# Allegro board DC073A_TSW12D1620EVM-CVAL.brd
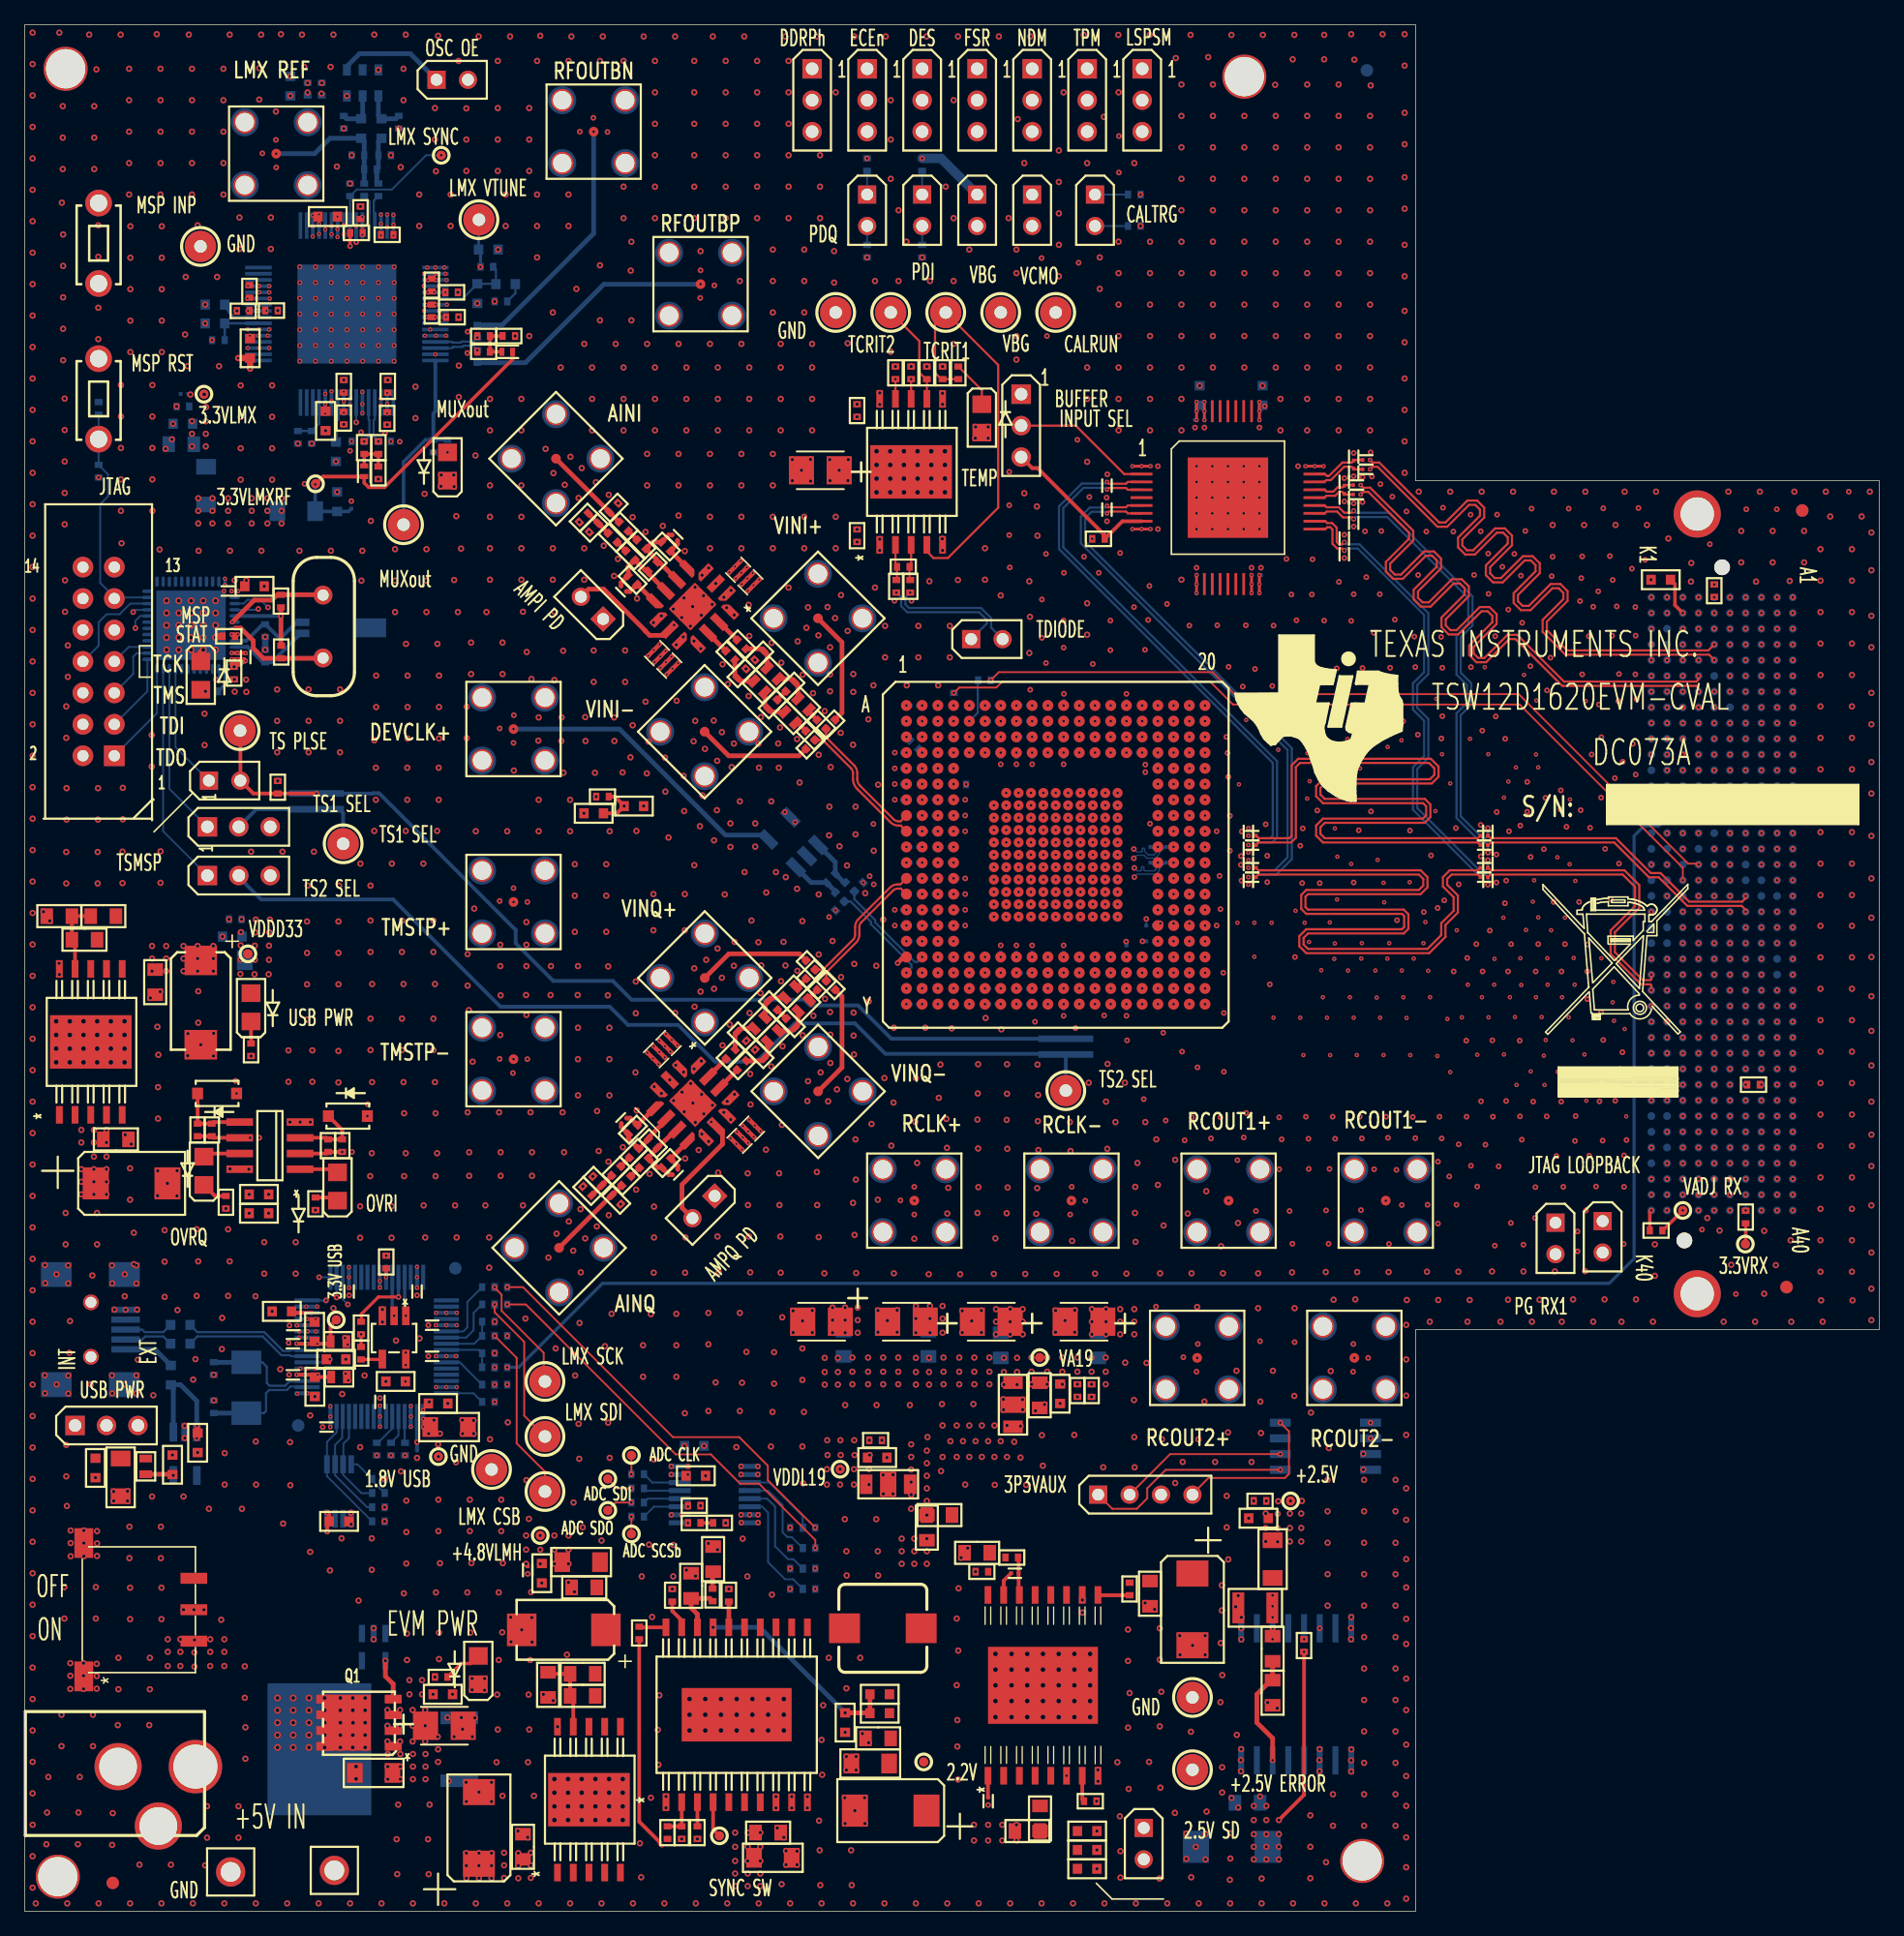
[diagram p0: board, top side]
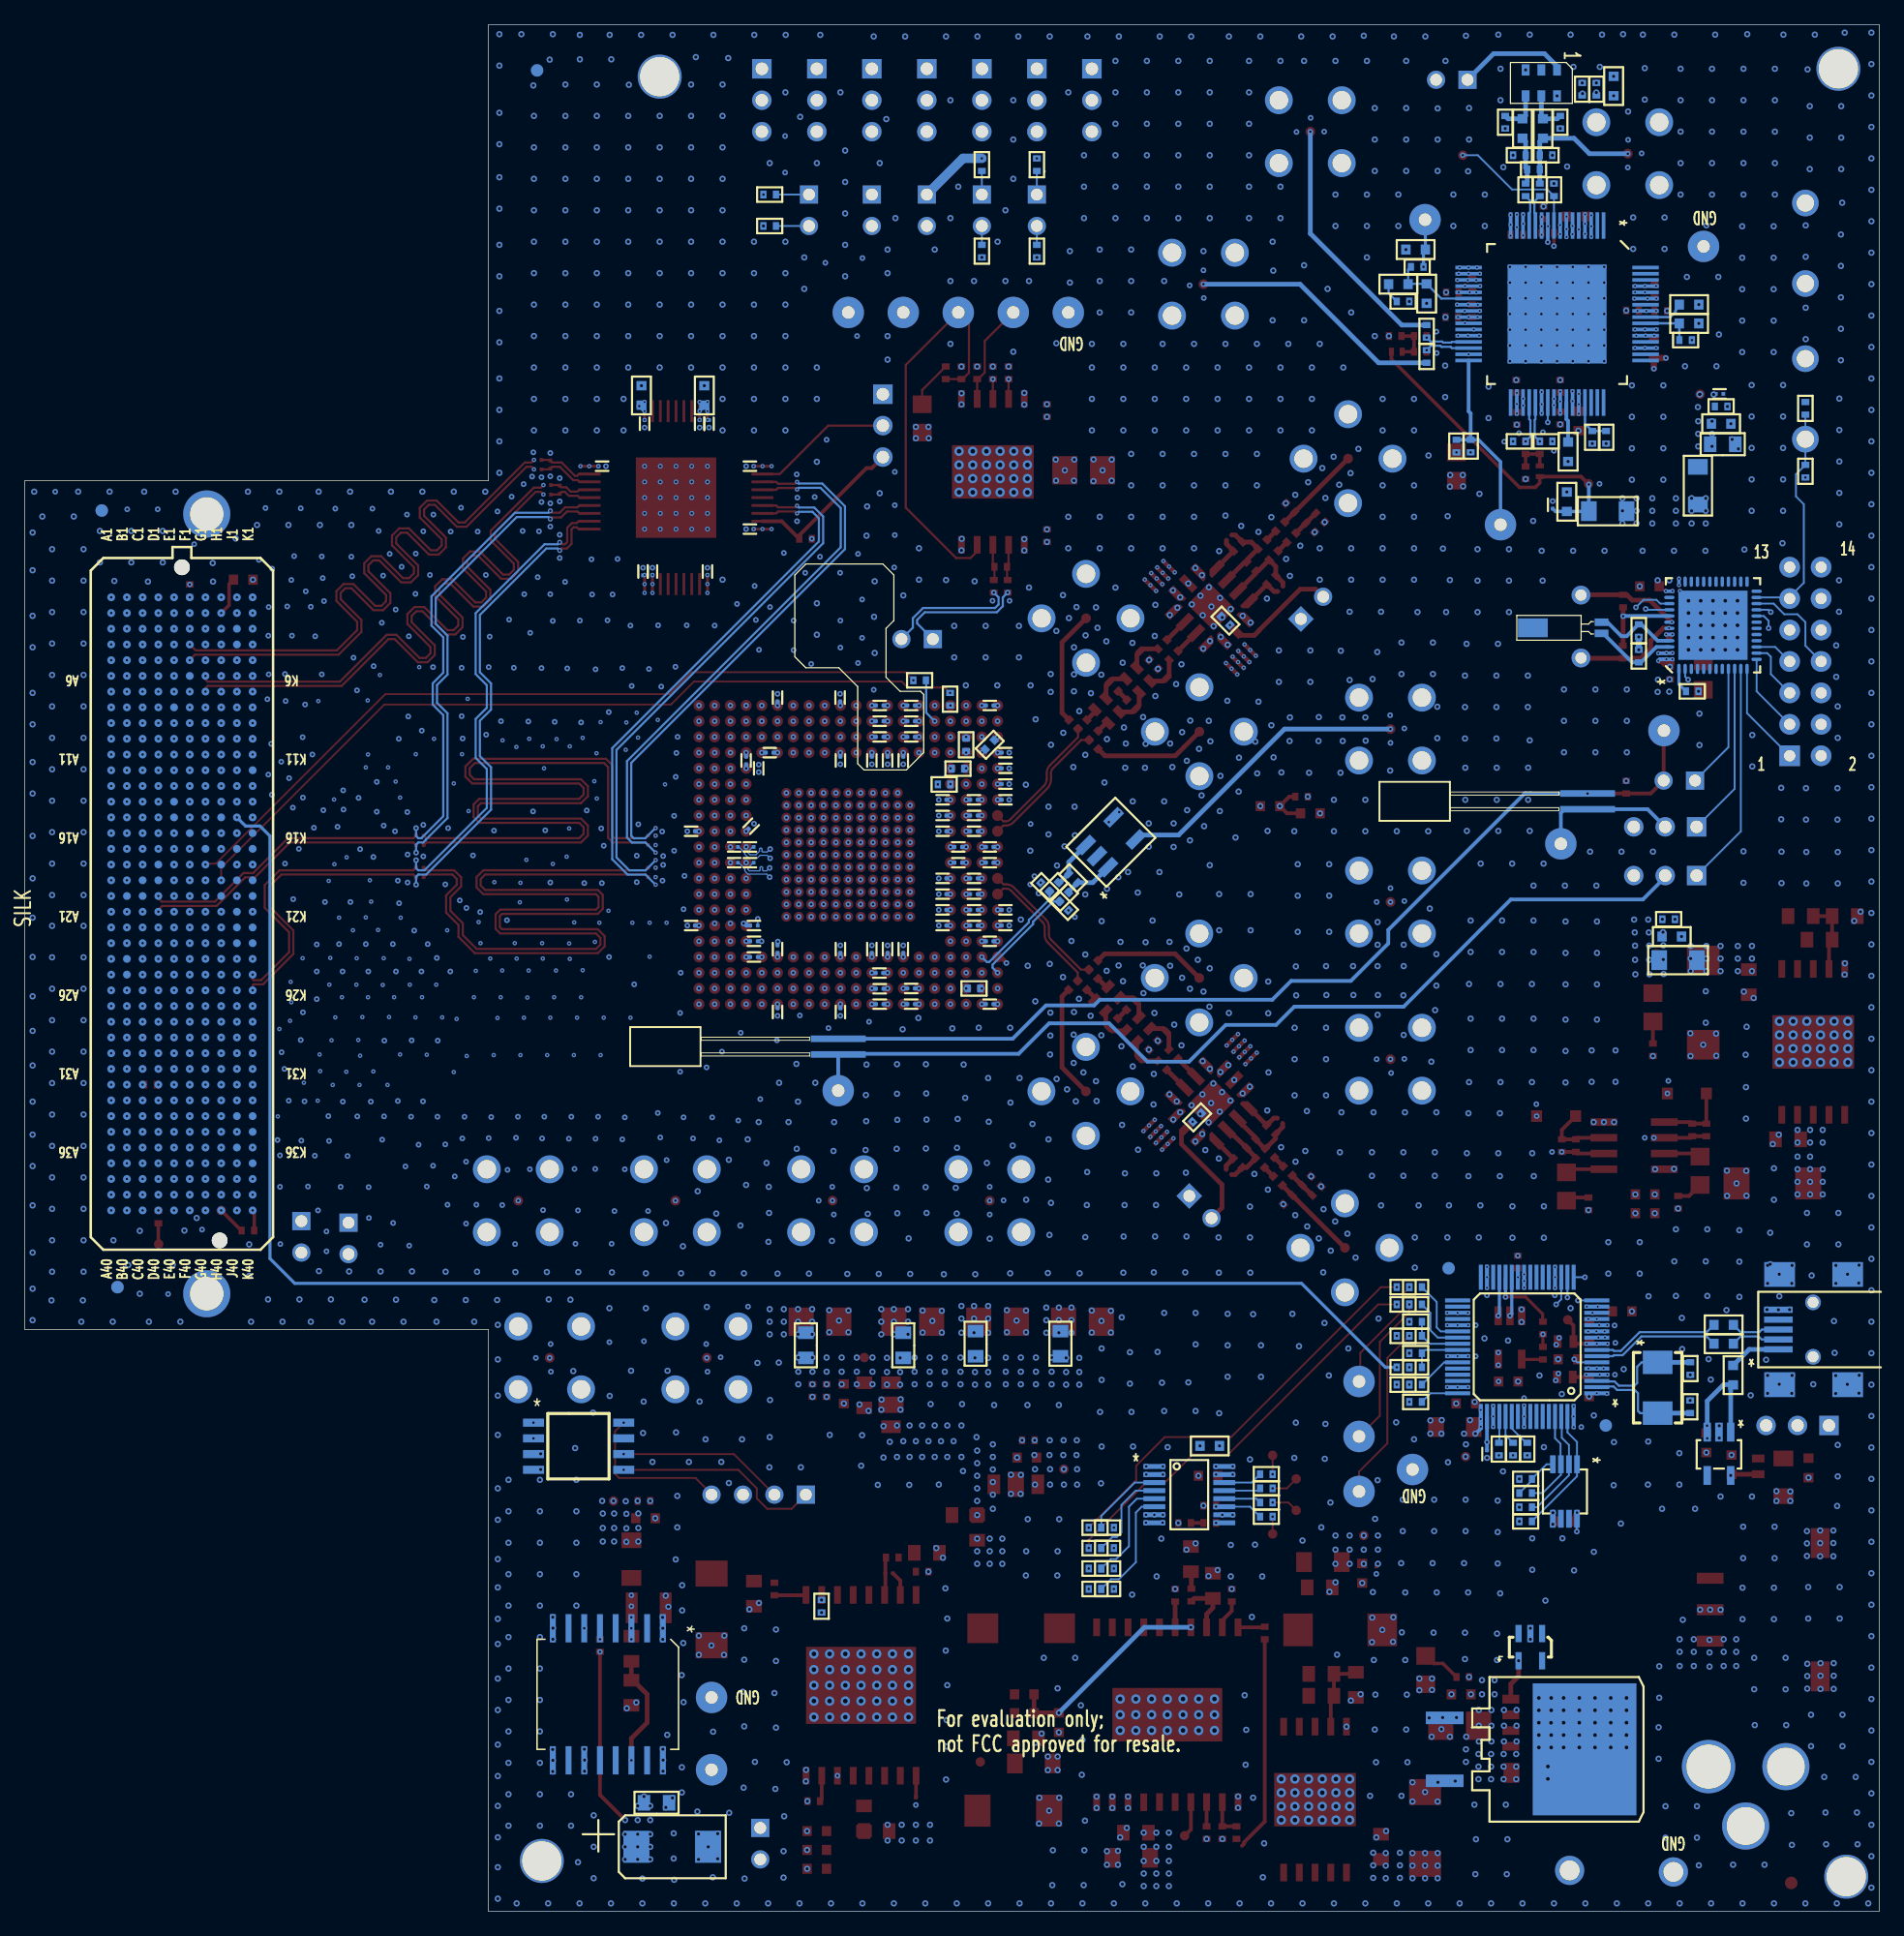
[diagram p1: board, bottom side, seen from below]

Outline 149.86 x 152.4 mm; copper layers: TOP, L02_GND1, L03_PWR, L04_GND2, L05_SIG1, L06_GND3, L07_GND4, L08_SIG2, L09_GND5, L10_SIG3, L11_GND6, BOTTOM. Coordinates in mm from the lower left corner of the outline.
Outline path: 0,152.4 0,0 112.39,0 112.39,46.99 149.86,46.99 149.86,115.57 112.39,115.57 112.39,152.4 0,152.4

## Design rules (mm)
net group CLK: nets CLKN CLKP
net group DCLK_RST: nets DCLK_RST+ DCLK_RST-
net group DCLKI: nets DCLKIN DCLKIP
net group DCLKQ: nets DCLKQN DCLKQP
net group DIFFPAIR10: nets N21135675 N21135677
net group DP1: nets N21321463 N21321475
net group DP2: nets N21375615 N21375619
net group DP3: nets N21135903 N21135906
net group DP4: nets DCLKI+ DCLKI-
net group DP5: nets DCLKQ+ DCLKQ-
net group DP6: nets N21451692 N21451698
net group DP7: nets N21540492 N21540508
net group DP19: nets LMX_CLKM LMX_CLKP
net group LMX_OSC: nets LMX_OSCN LMX_OSCP
net group ORI: nets ORI+ ORI-
net group ORQ: nets ORQ+ ORQ-
net group OSCIO: nets OSCI OSCO
net group OVRI: nets OVRI+ OVRI-
net group OVRQ: nets OVRQ+ OVRQ-
net group RCLK: nets RCLK+ RCLK-
net group RCOUT1: nets RCOUT1+ RCOUT1-
net group RCOUT2: nets RCOUT2+ RCOUT2-
net group TDIODE: nets TDIODE+ TDIODE-
net group VINI: nets VINI+ VINI-
net group VINQ: nets VINQ+ VINQ-
net group MG2: nets DI0+ DI0- DI1+ DI1- DI2+ DI2- DI3+ DI3- DI4+ DI4- DI5+ DI5- DI6+ DI6- DI7+ DI7- DI8+ DI8- DI9+ DI9- DI10+ DI10- DI11+ DI11- DID0+ DID0- DID2+ DID2- DID3+ DID3- DID4+ DID4- DID5+ DID5- DID6+ DID6- DID7+ DID7- DID8+ DID8- DID9+ DID9- DID10+ DID10- DID11+ DID11- DQ0+ DQ0- DQ1+ DQ1- DQ2+ DQ2- DQ3+ DQ3- DQ4+ DQ4- DQ5+ DQ5- DQ6+ DQ6- DQ7+ DQ7- DQ8+ DQ8- DQ9+ DQ9- DQ10+ DQ10- DQ11+ DQ11- DQD0+ DQD0- DQD1+ DQD1- DQD2+ DQD2- DQD3+ DQD3- DQD4+ DQD4- DQD5+ DQD5- DQD6+ DQD6- DQD7+ DQD7- DQD8+ DQD8- DQD9+ DQD9- DQD10+ DQD10- DQD11+ DQD11-

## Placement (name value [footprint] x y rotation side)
C1  .1uF  [0402]  48.4 111.86 315 top
C2  .1uF  [0402]  64.39 95.88 315 top
C3  .01uF  [0201]  52.53 110.96 135 top
C4  1pF  [0402]  59.36 101.45 225 top
C5  2.7pF  [0402]  61.87 98.93 225 top
C6  .1uF  [0402]  47.5 110.96 315 top
C7  1pF  [0402]  57.92 100.01 225 top
C8  2.7pF  [0402]  60.44 97.49 225 top
C9  .01uF  [0306]  58.64 107.37 315 top
C10  2200pF  [0306]  57.65 108.36 135 top
C11  .01uF  [0306]  52.08 100.64 315 top
C12  2200pF  [0306]  51.1 101.62 135 top
C13  .01uF  [0201]  48.4 106.83 135 top
C14  .1uF  [0402]  63.49 94.98 315 top
C15  .01uF  [0402]  46.69 90.04 180 top
C16  .1uF  [0402]  47.8 59.81 45 top
C17  .1uF  [0402]  63.51 75.71 45 top
C18  .01uF  [0201]  48.42 63.85 225 top
C19  1pF  [0402]  57.94 70.68 315 top
C20  2.7pF  [0402]  60.46 73.19 315 top
C21  1pF  [0402]  59.38 69.24 315 top
C22  2.7pF  [0402]  61.9 71.75 315 top
C23  .01uF  [0201]  52.56 59.72 225 top
C24  .1uF  [0402]  64.41 74.81 45 top
C25  .01uF  [0306]  52.02 70.14 45 top
C26  2200pF  [0306]  51.03 69.15 225 top
C27  .01uF  [0306]  58.75 63.23 45 top
C28  2200pF  [0306]  57.76 62.24 225 top
C29  .1uF  [0402]  48.6 59.01 45 top
C30  0.1uF  [0603]  18.92 57.91 0 top
C31  1uF  [0603]  18.92 56.39 0 top
C32  .1uF  [0402]  24.51 61.85 270 top
C33  .1uF  [0402]  15.11 63.12 270 top
C34  100pF  [0402]  67.26 121.23 270 top
C35  .1uF  [0402]  67.26 111.12 90 top
C36  10uF  [TANT_B]  64.29 116.41 180 top
C37  100pF  [0402]  70.99 108.61 0 top
C38  .1uF  [0402]  75.56 91.03 180 bottom
C39  .1uF  [0402]  74.45 92.3 180 bottom
C40  4700pF  [0402]  66.68 82.74 315 bottom
C41  4700pF  [0402]  67.4 82.74 225 bottom
C42  4700pF  [0402]  65.87 81.22 45 bottom
C43  4700pF  [0402]  65.87 81.93 315 bottom
C44  10uF  [0603]  100.03 122.45 90 bottom
C45  1uF  [0603]  94.95 122.45 90 bottom
C46  .1uF  [0201]  95.33 120.17 90 bottom
C47  .1uF  [0201]  94.56 120.17 90 bottom
C48  .1uF  [0201]  91.26 116.74 180 bottom
C49  .1uF  [0201]  91.26 111.66 180 bottom
C50  .1uF  [0201]  94.69 108.23 270 bottom
C51  .1uF  [0201]  99.9 108.23 270 bottom
C52  .1uF  [0201]  99.14 108.23 270 bottom
C53  0.1uF  [0201]  108.41 117.25 0 top
C54  0.1uF  [0201]  108.41 116.48 0 top
C55  .1uF  [0201]  99.77 120.17 90 bottom
C56  .1uF  [0201]  103.2 116.74 0 bottom
C57  0.1uF  [0201]  107.65 115.21 0 top
C58  0.1uF  [0201]  107.65 114.45 0 top
C59  0.1uF  [0201]  118.24 87.2 270 top
C60  0.1uF  [0201]  118.24 85.83 90 top
C61  0.1uF  [0201]  118.24 84.61 270 top
C62  0.1uF  [0201]  118.24 83.24 90 top
C63  .1uF  [0201]  73.15 89.79 180 bottom
C64  .1uF  [0201]  70.61 89.79 180 bottom
C65  .1uF  [0201]  73.15 88.52 0 bottom
C66  .1uF  [0201]  73.15 87.25 180 bottom
C67  .1uF  [0201]  74.42 85.98 0 bottom
C68  .1uF  [0201]  74.42 84.71 0 bottom
C69  .1uF  [0201]  73.15 83.44 180 bottom
C70  .1uF  [0201]  73.15 82.17 0 bottom
C71  .1uF  [0201]  73.15 80.9 180 bottom
C72  .1uF  [0201]  70.61 80.9 180 bottom
C73  .1uF  [0201]  75.69 80.9 0 bottom
C74  .1uF  [0201]  73.15 79.63 180 bottom
C75  .1uF  [0201]  75.69 79.63 0 bottom
C76  .1uF  [0201]  75.69 89.79 0 bottom
C77  10uF  [TANT_B]  64.39 47.62 180 top
C78  .1uF  [0201]  78.23 96.14 0 bottom
C79  .1uF  [0201]  78.23 97.41 0 bottom
C80  .1uF  [0201]  71.88 97.41 180 bottom
C81  .1uF  [0201]  78.23 94.87 180 bottom
C82  .1uF  [0201]  80.14 92.96 270 bottom
C83  .1uF  [0201]  81.41 92.96 270 bottom
C84  .1uF  [0201]  70.61 93.6 180 bottom
C85  .1uF  [0201]  70.61 92.33 180 bottom
C86  .1uF  [0201]  75.69 88.52 0 bottom
C87  .1uF  [0201]  70.61 91.06 180 bottom
C88  .1uF  [0201]  75.69 82.17 0 bottom
C89  .1uF  [0201]  70.61 79.63 180 bottom
C90  .1uF  [0201]  71.88 78.36 0 bottom
C91  .1uF  [0201]  71.88 73.28 180 bottom
C92  .1uF  [0201]  78.23 74.55 0 bottom
C93  .1uF  [0201]  78.23 73.28 0 bottom
C94  .1uF  [0201]  80.14 77.72 90 bottom
C95  .1uF  [0201]  81.41 77.72 90 bottom
C96  10uF  [TANT_B]  71.25 47.62 180 top
C97  .1uF  [0201]  83.97 98.04 90 bottom
C98  .1uF  [0201]  83.95 92.96 270 bottom
C99  .1uF  [0201]  89.03 98.04 90 bottom
C100  .1uF  [0201]  89.66 93.6 0 bottom
C101  .1uF  [0201]  91.57 92.96 270 bottom
C102  .1uF  [0201]  91.16 87.66 135 bottom
C103  .1uF  [0201]  96.01 87.25 0 bottom
C104  .1uF  [0201]  90.93 79.63 180 bottom
C105  .1uF  [0201]  90.93 78.36 180 bottom
C106  .1uF  [0201]  83.95 77.72 90 bottom
C107  .1uF  [0201]  83.95 72.64 270 bottom
C108  .1uF  [0201]  89.03 77.72 90 bottom
C109  .1uF  [0201]  90.93 77.09 0 bottom
C110  .1uF  [0201]  89.03 72.64 270 bottom
C111  .1uF  [0201]  96.01 79.63 0 bottom
C112  .1uF  [0201]  90.55 92.33 270 bottom
C113  10uF  [TANT_B]  85.6 47.62 180 top
C114  .1uF  [0201]  71.88 84.71 180 bottom
C115  .1uF  [0201]  75.69 83.44 0 bottom
C116  .1uF  [0201]  78.87 77.72 90 bottom
C117  .1uF  [0201]  80.77 97.41 0 bottom
C118  .1uF  [0201]  80.77 96.14 180 bottom
C119  .1uF  [0201]  80.77 94.87 0 bottom
C120  .1uF  [0201]  80.8 75.79 0 bottom
C121  .1uF  [0201]  80.77 74.52 180 bottom
C122  .1uF  [0201]  80.77 73.28 0 bottom
C123  10uF  [TANT_B]  78.11 47.62 180 top
C124  .1uF  [0201]  78.87 92.96 270 bottom
C125  .1uF  [0201]  75.69 87.25 0 bottom
C126  .1uF  [0201]  71.88 85.98 180 bottom
C127  10uF  [0603]  21.46 147.45 90 bottom
C128  .1uF  [0402]  27.43 139.06 90 bottom
C129  1uF  [0402]  22.86 147.19 270 bottom
C130  1800pF  [0603]  15.37 128.27 180 bottom
C131  .068uF  [0603]  38.86 131.44 0 bottom
C132  390pF  [0603]  36.58 130.68 270 bottom
C133  .1uF  [0402]  24 147.19 270 bottom
C134  300pF  [0603]  37.47 134.24 0 bottom
C135  .1uF  [0402]  28.57 139.06 90 bottom
C136  .1uF  [0402]  26.92 118.75 180 bottom
C137  .1uF  [0402]  28.57 116.2 270 top
C138  .1uF  [0402]  36.58 125.6 270 bottom
C139  .1uF  [0402]  29.34 123.19 90 top
C140  .1uF  [0402]  29.08 118.75 0 bottom
C141  1uF  [0402]  26.8 135.59 180 top
C142  .1uF  [0402]  39.12 127.25 0 top
C143  1uF  [0402]  32.89 131.37 90 top
C144  .1uF  [0402]  36.58 127.64 90 bottom
C145  1uF  [0402]  32.89 129.29 90 top
C146  1uF  [0402]  19.94 129.31 0 top
C147  1uF  [0402]  29.29 135.43 180 top
C148  1uF  [0402]  18.16 130.86 270 top
C149  1uF  [0402]  25.78 123.19 90 top
C150  10uF  [0603]  15.37 129.79 180 bottom
C151  10uF  [0603]  24.49 136.91 0 top
C152  10uF  [0603]  24.31 120.4 90 top
C153  10uF  [0603]  25.15 117.91 90 bottom
C154  10uF  [0603]  18.21 126.26 90 top
C155  1uF  [0402]  139.7 66.78 180 top
C156  0.1uF  [0603]  54.1 37.59 0 bottom
C157  0.1uF  [0603]  54.23 35.18 0 top
C158  10uF  [0603]  23.44 42.37 270 top
C159  .1uF  [0201]  21.67 43.33 180 top
C160  10uF  [0603]  23.42 46.81 90 top
C161  .1uF  [0201]  21.67 45.85 180 top
C162  .1uF  [0201]  31.7 36.93 270 bottom
C163  1uF  [0603]  11.94 36.07 90 top
C164  100uF  [1206]  7.75 35.05 270 top
C165  0.1uF  [0603]  5.71 35.81 270 top
C166  0.1uF  [0603]  29.97 42.8 180 top
C167  1uF  [0603]  13.97 37.85 270 top
C168  100uF  [1206]  34.29 39.12 0 top
C169  10uF  [0603]  33.4 41.02 0 top
C170  1uF  [0603]  25.4 31.5 0 top
C171  .1uF  [0201]  24.38 39.12 180 top
C172  .1uF  [0201]  21.69 47.32 180 top
C173  .1uF  [0201]  32.92 47.35 180 top
C174  18pF  [0402]  15.28 40.75 90 bottom
C175  18pF  [0402]  15.27 43.84 270 bottom
C176  .1uF  [0201]  28.7 41.15 90 top
C177  .1uF  [0201]  26.21 50.06 270 top
C178  .1uF  [0201]  31.7 50.06 270 top
C179  .1uF  [0201]  32.92 44.83 180 top
C180  47uF  [TANT_B]  33.91 14.99 0 top
C181  10uF  [0603]  33.78 17.53 0 top
C182  22uF  [1206]  60.45 4.32 0 top
C183  10uF  [0805]  60.07 6.35 0 top
C184  .47uF  [0402]  56.9 25.53 90 top
C185  .1uF  [0805]  68.96 13.97 180 top
C186  47uF  [1206]  68.33 11.94 180 top
C187  330uF  [TANT_D]  69.98 8.13 180 top
C188  270pF  [0603]  69.09 16 180 top
C189  12nF  [0402]  52.32 25.53 90 top
C190  91pF  [0805]  53.85 26.29 90 top
C191  .027uF  [0805]  55.63 28.45 90 top
C192  10uF  [0603]  68.88 36.65 0 top
C193  1uF  [0402]  68.76 38.05 0 top
C194  10uF  [0603]  85.85 4.95 0 top
C195  10uF  [0603]  85.85 3.43 0 top
C196  10uF  [0603]  85.85 6.48 0 top
C197  .01uF  [0201]  80.01 27.3 0 top
C198  .1uF  [0805]  90.93 25.65 270 top
C199  220uF  [TANT_D]  94.36 24.38 270 top
C200  33uF  [0805]  82.02 41.68 270 top
C201  10uF  [0603]  83.67 41.81 270 top
C202  1uF  [0402]  85.06 42.06 270 top
C203  .1uF  [0402]  86.21 42.06 270 top
C204  1000pF  [0805]  76.96 28.96 180 top
C205  2200pF  [0201]  77.85 8.89 270 top
C206  15uF  [TANT_X]  97.54 5.21 180 bottom
C207  1uF  [0805]  98.81 8.76 180 bottom
C208  10uF  [0603]  99.69 31.75 180 top
C209  .1uF  [0402]  99.82 33.15 180 top
C210  .1uF  [1210]  99.44 24.51 180 top
C211  10uF  [0603]  16.76 78.74 180 bottom
C212  .1uF  [0402]  17.02 80.14 180 bottom
C213  15uF  [TANT_X]  8.64 58.8 0 top
C214  1uF  [0805]  7.37 62.36 0 top
C215  470pF  [0805]  4.83 78.49 180 top
C216  150uF  [7343]  14.22 73.41 270 top
C217  15uF  [0805]  10.54 75.06 270 top
C218  33uF  [0805]  12.65 118.52 180 bottom
C219  10uF  [0603]  12.78 120.17 180 bottom
C220  .1uF  [0402]  12.78 121.56 180 bottom
C221  .01uF  [0201]  12.9 122.58 180 bottom
C222  10uF  [0603]  25.25 113.87 90 bottom
C223  .01uF  [0201]  26.39 113.61 90 bottom
C224  15uF  [TANT_X]  36.7 6.73 90 top
C225  1uF  [0805]  40.26 5.21 90 top
C226  470pF  [0805]  45.09 17.4 180 top
C227  150uF  [7343]  43.56 22.73 180 top
C228  15uF  [0805]  45.21 26.16 180 top
C229  10uF  [0603]  41.78 27.3 270 top
C230  .01uF  [0201]  40.64 27.56 270 top
C231  10pF  [0402]  19.43 101.4 90 bottom
C232  10pF  [0402]  19.43 103.45 270 bottom
C233  .1uF  [0201]  17.86 101.32 90 top
C234  27pF  [0402]  20.73 101.73 90 top
C235  27pF  [0402]  20.7 105.84 270 top
C236  .1uF  [0201]  16.41 106.65 180 top
C237  1uF  [0603]  18.57 107.04 0 top
C238  .001uF  [0402]  5.97 121.41 90 bottom
D1  LED ORANGE  [LED_0805]  25.27 58.55 270 top
D2  1N4148W  [DIODE_SM_1N4148W]  26.11 64.24 180 top
D3  LED ORANGE  [LED_0805]  14.48 59.82 270 top
D4  1N4148W  [DIODE_SM_1N4148W]  15.54 66.07 180 top
D5  LED RED  [LED_0805]  77.34 120.6 90 top
D6  LED GREEN  [LED_0805]  34.16 116.71 270 top
D7  LED GREEN  [LED_0805]  18.29 73.03 270 top
D8  LED GREEN  [LED_0805]  36.65 19.48 270 top
D9  MBRB2515L  [DIODE_MBRB2515L]  29.46 13.08 0 bottom
D10  LED GREEN  [LED_0805]  14.22 99.82 90 top
F1  FUSE 10A 63V FAST  [1206]  28.19 11.18 0 top
FB1  120 OHM @ 100MHz  [IND_0603]  25.4 43.15 180 top
FB2  120 OHM @ 100MHz  [IND_0603]  25.35 46.02 180 top
FB3  26 OHM @ 100MHz  [IND_0603]  9.78 35.94 90 top
FB4  27uF  [1206_BEAD_NFM31P]  69.77 34.49 180 top
FB5  27uF  [1206_BEAD_NFM31P]  79.86 40.92 90 top
FB6  120 OHM @ 100MHz  [1206]  100.84 28.45 90 top
FB7  120 OHM @ 100MHz  [1206]  16.26 76.83 0 bottom
FB8  120 OHM @ 100MHz  [1206]  14.66 115.16 90 bottom
FB9  120 OHM @ 100MHz  [1206]  21.95 113.11 0 bottom
FB10  120 OHM @ 100MHz  [1206]  44.96 28.21 180 top
J1  SMA, THVT, SMT CENTER PIN  [SMA_THVT_SMT_250X250]  64.1 104.45 315 top
J2  SMA, THVT, SMT CENTER PIN  [SMA_THVT_SMT_250X250]  42.93 117.35 315 top
J3  SMA, THVT, SMT CENTER PIN  [SMA_THVT_SMT_250X250]  54.94 95.29 315 top
J4  SMA, THVT, SMT CENTER PIN  [SMA_THVT_SMT_250X250]  54.95 75.4 45 top
J5  SMA, THVT, SMT CENTER PIN  [SMA_THVT_SMT_250X250]  43.18 53.59 45 top
J6  SMA, THVT, SMT CENTER PIN  [SMA_THVT_SMT_250X250]  64.11 66.24 45 top
J7  HDR, THVT, 2POS, .100, GOLD  [HDR_THVT_1X2_100_M]  72.52 138.68 0 top
J8  HDR, THVT, 2POS, .100, GOLD  [HDR_THVT_1X2_100_M]  68.07 138.68 0 top
J9  HDR, THVT, 2POS, .100, GOLD  [HDR_THVT_1X2_100_M]  86.49 138.68 0 top
J10  HDR, THVT, 2POS, .100, GOLD  [HDR_THVT_1X2_100_M]  81.41 138.68 0 top
J11  HDR, THVT, 2POS, .100, GOLD  [HDR_THVT_1X2_100_M]  76.48 102.77 90 top
J12  HDR, THVT, 2POS, .100, GOLD  [HDR_THVT_1X2_100_M]  76.96 138.68 0 top
J13  SMA, THVT, SMT CENTER PIN  [SMA_THVT_SMT_250X250]  39.5 81.53 0 top
J14  SMA, THVT, SMT CENTER PIN  [SMA_THVT_SMT_250X250]  71.88 57.4 0 top
J15  SMA, THVT, SMT CENTER PIN  [SMA_THVT_SMT_250X250]  97.28 57.4 0 top
J16  SMA, THVT, SMT CENTER PIN  [SMA_THVT_SMT_250X250]  39.5 68.83 0 top
J17  SMA, THVT, SMT CENTER PIN  [SMA_THVT_SMT_250X250]  84.58 57.4 90 top
J18  SMA, THVT, SMT CENTER PIN  [SMA_THVT_SMT_250X250]  109.98 57.4 90 top
J19  SMA, THVT, SMT CENTER PIN  [SMA_THVT_SMT_250X250]  94.74 44.7 90 top
J20  SMA, THVT, SMT CENTER PIN  [SMA_THVT_SMT_250X250]  107.44 44.7 90 top
J21  SMA, THVT, SMT CENTER PIN  [SMA_THVT_SMT_250X250]  39.5 95.5 270 top
J22  SMA, THVT, SMT CENTER PIN  [SMA_THVT_SMT_250X250]  20.32 141.99 0 top
J24  HDR, THVT, 2POS, .100  [HDR_THVT_1X2_100_M]  33.27 147.96 90 top
J26  SMA, THVT, SMT CENTER PIN  [SMA_THVT_SMT_250X250]  54.61 131.44 0 top
J27  SMA, THVT, SMT CENTER PIN  [SMA_THVT_SMT_250X250]  45.97 143.76 0 top
J28  CON, SMVT, HS, FIELD ARRAY, FMC, MALE  [CON_SMVT_40X10_SEAM_MTG]  137.16 81.38 90 bottom
J29  HDR, THVT, 2POS, .100, GOLD  [HDR_THVT_1X2_100_M]  123.7 55.63 0 top
J30  HDR, THVT, 4POS, .100, GOLD  [HDR_THVT_1X4_100_M]  86.74 33.66 90 top
J31  HDR, THVT, 2POS, .100, GOLD  [HDR_THVT_1X2_100_M]  127.51 55.75 0 top
J32  CON, USB, MINI, AB, SMT  [CON_SMRT_USBMNE20_F]  4.7 46.99 0 bottom
J33  CONN, JACK, PWR, MINI, R/A, TH  [CON_RAPC722_JACK_THVT_3]  10.67 11.68 270 top
J34  HDR, THVT, 2POS, .100, GOLD  [HDR_THVT_1X2_100_M]  90.42 6.73 0 top
J35  HDR, THVT, 2POS, .100, GOLD  [HDR_THVT_1X2_100_M]  14.88 91.34 90 top
J36  HDR, Shrouded, 14 POS STRGHT GOLD  [CON_THVT_2X7_100_M_SHROUDED_KEY]  7.24 95.89 180 top
JP1  JUMPER_1X2_100  [HDR_THVT_1X2_100_M]  46.74 104.39 225 top
JP2  JUMPER_1X2_100  [HDR_THVT_1X2_100_M]  55.75 57.78 315 top
JP3  JUMPER_1X3_100  [HDR_THVT_1X3_100_M]  90.3 148.84 0 top
JP4  JUMPER_1X3_100  [HDR_THVT_1X3_100_M]  85.85 148.84 0 top
JP5  JUMPER_1X3_100  [HDR_THVT_1X3_100_M]  81.41 148.84 0 top
JP6  JUMPER_1X3_100  [HDR_THVT_1X3_100_M]  76.96 148.84 0 top
JP7  JUMPER_1X3_100  [HDR_THVT_1X3_100_M]  72.52 148.84 0 top
JP8  JUMPER_1X3_100  [HDR_THVT_1X3_100_M]  68.07 148.84 0 top
JP9  JUMPER_1X3_100  [HDR_THVT_1X3_100_M]  63.63 148.84 0 top
JP10  JUMPER_1X3_100  [HDR_THVT_1X3_100_M]  80.52 122.56 0 top
JP11  HDR, THVT, 3POS, .100, GOLD  [HDR_THVT_1X3_100_M]  4.06 39.24 90 top
JP12  JUMPER_1X3_100  [HDR_THVT_1X3_100_M]  14.76 87.6 90 top
JP13  JUMPER_1X3_100  [HDR_THVT_1X3_100_M]  14.76 83.67 90 top
L1  6.8nH  [IND_0603]  60.44 100.01 315 top
L2  3.6nH  [IND_0603]  62.93 97.52 315 top
L3  6.8nH  [IND_0603]  59.36 98.93 315 top
L4  3.6nH  [IND_0603]  61.85 96.44 315 top
L5  6.8nH  [IND_0603]  59.38 71.76 45 top
L6  3.6nH  [IND_0603]  61.87 74.25 45 top
L7  6.8nH  [IND_0603]  60.46 70.68 45 top
L8  3.6nH  [IND_0603]  62.95 73.17 45 top
L9  18nH  [IND_0402]  27.43 116.33 270 top
L10  18nH  [IND_0402]  38.99 125.98 0 top
L11  1.5uH  [IND_SM_6P7MMX6P7MM]  69.34 22.86 0 top
MT1  STANDOFF, FEMALE, 4-40 X 1 3/16", AL  [MFG125_PLATED]  2.67 2.79 0 top
MT2  STANDOFF, FEMALE, 4-40 X 1 3/16", AL  [MFG125_PLATED]  3.3 148.84 0 top
MT3  STANDOFF, FEMALE, 4-40 X 1 3/16", AL  [MFG125_PLATED]  98.55 148.21 0 top
MT4  STANDOFF, FEMALE, 4-40 X 1 3/16", AL  [MFG125_PLATED]  108.08 4.06 0 top
NOREF  -  []  112.39 0 90 top
NOREF#2  -  []  -99.82 372.26 0 top
NOREF#3  -  []  238.12 58.42 0 top
NOREF#4  -  [unnamed#2]  7.11 2.29 0 top
NOREF#5  -  []  -37.52 8.19 0 top
NOREF#6  -  [unnamed#2]  143.64 113.16 0 top
NOREF#7  -  []  0 0 90 top
NOREF#8  -  []  128.45 76.58 0 top
NOREF#9  -  []  -33.18 -7.81 0 top
NOREF#10  -  []  0 0 0 top
NOREF#11  -  []  -110.52 -102.23 0 top
NOREF#12  -  []  0 152.4 0 top
NOREF#13  -  []  105.87 96.93 0 top
NOREF#14  -  []  112.39 115.57 90 top
NOREF#15  -  [unnamed#2]  142.37 50.42 0 top
NOREF#16  -  []  105.08 71.63 0 top
NOREF#17  -  []  149.86 46.99 90 top
NOREF#18  -  [unnamed#2]  143.64 113.16 180 bottom
NOREF#19  -  []  187.12 16.48 180 bottom
NOREF#20  -  [unnamed#2]  108.46 148.72 180 bottom
NOREF#21  -  []  103.68 136.73 180 bottom
NOREF#22  -  [unnamed#2]  142.37 50.42 180 bottom
PP1  PROBE POINT  [PROBE_POINT_30PAD]  33.66 141.86 0 top
PP2  PROBE POINT  [PROBE_POINT_30PAD]  133.99 56.62 0 top
PP3  PROBE POINT  [PROBE_POINT_30PAD]  139.04 53.9 0 top
PP4  PROBE POINT  [PROBE_POINT_30PAD]  47.12 34.92 0 top
PP5  PROBE POINT  [PROBE_POINT_30PAD]  47.12 32.38 0 top
PP6  PROBE POINT  [PROBE_POINT_30PAD]  25.17 47.78 0 top
PP7  PROBE POINT  [PROBE_POINT_30PAD]  49.02 36.83 0 top
PP8  PROBE POINT  [PROBE_POINT_30PAD]  49.02 30.48 0 top
PP9  PROBE POINT  [PROBE_POINT_30PAD]  33.43 36.73 0 top
PP10  PROBE POINT  [PROBE_POINT_30PAD]  72.64 12.06 0 top
PP11  PROBE POINT  [PROBE_POINT_30PAD]  56.13 6.1 90 top
PP12  PROBE POINT  [PROBE_POINT_30PAD]  65.89 35.71 90 top
PP13  PROBE POINT  [PROBE_POINT_30PAD]  82.02 44.73 0 top
PP14  PROBE POINT  [PROBE_POINT_30PAD]  18.03 77.34 0 top
PP15  PROBE POINT  [PROBE_POINT_30PAD]  14.48 122.56 0 top
PP16  PROBE POINT  [PROBE_POINT_30PAD]  23.5 115.32 90 top
PP17  PROBE POINT  [PROBE_POINT_30PAD]  41.66 30.35 0 top
PP18  PROBE POINT  [PROBE_POINT_30PAD]  102.29 33.15 0 top
Q1  CSD18532Q5  [SON_Q5B_8]  27.01 15.23 180 top
R1  0  [0402]  65.11 95.88 225 top
R2  200  [0402]  51.82 110.25 315 top
R3  12.1  [0402]  49.84 110.43 315 top
R4  40.2  [0402]  57.92 102.34 315 top
R5  1.1k  [0402]  47.59 113.39 45 top
R6  200  [0402]  50.74 108.63 45 top
R7  12.1  [0402]  48.94 109.53 315 top
R8  1.1k  [0402]  45.17 112.58 225 top
R9  40.2  [0402]  57.02 101.45 315 top
R10  49.9  [0402]  45.98 111.77 225 top
R11  200  [0402]  49.12 107.55 315 top
R12  0  [0402]  63.49 94.26 45 top
R13  10k  [0402]  52.83 104.27 45 bottom
R14  1k  [0603]  49.23 89.28 180 top
R15  1k  [0603]  45.97 88.7 180 top
R16  0  [0402]  63.51 76.43 315 top
R17  200  [0402]  49.14 63.14 45 top
R18  12.1  [0402]  49.23 61.25 45 top
R19  40.2  [0402]  57.05 69.24 45 top
R20  1.1k  [0402]  45.46 58.2 135 top
R21  49.9  [0402]  46.27 59.01 135 top
R22  200  [0402]  50.76 62.03 135 top
R23  40.2  [0402]  57.94 68.34 45 top
R24  200  [0402]  51.84 60.44 45 top
R25  12.1  [0402]  50.04 60.44 45 top
R26  1.1k  [0402]  47.8 57.48 315 top
R27  0  [0402]  65.13 74.81 135 top
R28  10k  [0402]  55.12 64.14 135 bottom
R29  1k  [0402]  72.52 141.1 270 bottom
R30  1k  [0402]  68.07 141.1 270 bottom
R31  1M  [0402]  25.65 61.85 90 top
R32  10k  [0402]  72.52 134.11 270 bottom
R33  10k  [0402]  68.07 134.11 270 bottom
R34  1.2k  [0402]  23.5 57.15 270 top
R35  1k  [0402]  89.66 138.68 180 bottom
R36  1M  [0402]  13.97 63.12 90 top
R37  1.2k  [0402]  16.26 57.28 270 top
R38  10k  [0402]  89.66 136.14 0 bottom
R39  1.3k  [0402]  70.36 124.28 270 top
R40  1k  [0402]  77.55 99.44 0 bottom
R41  1.3k  [0402]  71.63 124.28 270 top
R42  3.3k  [0402]  73.79 94.23 90 bottom
R43  0  [0402]  70.43 107.04 270 top
R44  3.3k  [0402]  71.88 94.23 135 bottom
R45  0  [0402]  71.55 107.04 270 top
R46  1k  [0402]  75.08 97.92 90 bottom
R47  10k  [0402]  72.9 124.28 270 top
R48  10k  [0402]  74.17 124.28 270 top
R49  750  [0402]  75.44 124.28 270 top
R51  100k  [0402]  73.15 74.55 180 bottom
R53  100  [0402]  65.14 83.46 45 bottom
R54  1k  [0201]  92.53 84.71 180 bottom
R55  1k  [0201]  92.53 85.98 180 bottom
R56  1k  [0201]  91.26 85.98 180 bottom
R57  1k  [0201]  91.26 84.71 180 bottom
R61  120  [0201]  107.39 117.5 90 top
R62  120  [0201]  107.39 116.23 270 top
R64  0  [0201]  99.19 86.89 180 top
R65  0  [0201]  99.19 86.13 180 top
R67  120  [0201]  106.63 115.47 90 top
R68  120  [0201]  106.63 114.2 270 top
R70  100  [0201]  87.45 115.16 90 top
R71  120  [0201]  107.39 113.44 90 top
R72  120  [0201]  107.39 112.17 270 top
R73  0  [0201]  98.88 87.2 270 top
R75  0  [0201]  98.88 85.83 90 top
R77  120  [0201]  106.63 110.9 90 top
R78  120  [0201]  106.63 109.63 270 top
R79  100  [0201]  87.45 113.23 90 top
R80  0  [0201]  99.19 84.3 180 top
R81  0  [0201]  99.19 83.54 180 top
R82  0  [0201]  98.88 84.61 270 top
R83  0  [0201]  98.88 83.24 90 top
R84  0  [0402]  86.77 110.87 180 top
R85  0  [0805]  73.03 45.85 90 bottom
R86  0  [0805]  78.87 45.72 90 bottom
R87  0  [0805]  86.74 45.72 90 bottom
R88  0  [0805]  66.17 45.85 90 bottom
R89  18  [0402]  15.65 126.92 0 bottom
R90  0  [0402]  37.34 132.84 180 bottom
R91  49.9  [0402]  26.92 141.86 180 bottom
R92  150  [0402]  25.78 144.53 90 bottom
R93  100  [0402]  27.94 140.72 180 bottom
R94  150  [0402]  30.23 144.53 90 bottom
R95  68  [0402]  38.48 130.05 180 bottom
R96  49.9  [0402]  29.08 141.86 0 bottom
R97  49.9  [0402]  27.43 118.24 270 top
R98  0  [0402]  29.29 120.6 90 top
R99  49.9  [0402]  28.57 118.24 90 top
R100  49.9  [0402]  37.08 125.98 0 top
R101  0  [0402]  27.13 137.21 270 top
R102  1k  [0402]  26.29 139.06 90 bottom
R103  0  [0402]  34.49 130.78 180 top
R104  49.9  [0402]  37.08 127.25 180 top
R105  100  [0402]  33.02 118.36 270 bottom
R106  0  [0402]  34.54 128.78 180 top
R107  330  [0402]  34.16 118.36 270 bottom
R108  0  [0402]  17.65 129.29 0 top
R109  0  [0402]  25.78 120.62 90 top
R110  10k  [0402]  23.19 119.08 90 bottom
R111  10k  [0402]  22.07 119.08 270 bottom
R112  4.99k  [0402]  136.53 106.68 270 top
R113  100  [0603]  132.21 107.57 180 top
R114  0  [0402]  131.83 54.99 180 top
R115  0  [0402]  139.06 56.08 270 top
R116  0  [0402]  62.36 30.99 0 bottom
R117  0  [0402]  63.37 30.99 0 bottom
R118  270  [0402]  18.29 69.6 270 top
R119  10k  [0402]  54.1 32.77 180 top
R120  0  [0402]  62.36 29.34 0 bottom
R121  0  [0402]  63.37 29.34 0 bottom
R122  100  [0402]  49.53 35.31 180 bottom
R123  100  [0402]  49.53 34.16 180 bottom
R124  100  [0402]  49.53 33.02 180 bottom
R125  100  [0402]  49.53 31.88 180 bottom
R126  100  [0402]  54.1 31.37 0 top
R127  0  [0402]  56.13 31.37 0 top
R128  0  [0402]  62.36 27.69 0 bottom
R129  0  [0402]  63.37 27.69 0 bottom
R130  0  [0402]  62.36 26.04 0 bottom
R131  0  [0402]  63.37 26.04 0 bottom
R132  0  [0603]  11.81 43.31 90 bottom
R133  100  [0402]  27.18 45.09 90 top
R134  100  [0402]  29.21 52.45 90 top
R135  10  [0603]  12.57 45.85 0 bottom
R136  100  [0402]  27.18 47.12 270 top
R137  10  [0603]  12.57 47.37 0 bottom
R138  100  [0402]  37.47 50.42 0 bottom
R139  0  [0402]  38.48 50.42 0 bottom
R140  12k  [0603]  25.16 44.59 180 top
R141  10k  [0402]  37.47 45.09 180 bottom
R142  10k  [0402]  37.47 47.62 180 bottom
R143  100  [0402]  37.47 49.02 0 bottom
R144  0  [0402]  38.48 49.02 0 bottom
R145  10k  [0402]  28.57 34.92 180 bottom
R146  10k  [0402]  28.57 32.64 180 bottom
R147  10k  [0402]  28.57 31.5 180 bottom
R148  1k  [0603]  20.78 48.46 0 top
R149  100  [0402]  37.47 46.48 0 bottom
R150  100  [0402]  37.47 43.94 0 bottom
R151  100  [0402]  37.47 42.55 0 bottom
R153  0  [0402]  38.48 46.48 0 bottom
R155  100  [0402]  29.59 37.34 270 bottom
R156  0  [0402]  38.48 43.94 0 bottom
R157  2.2k  [0402]  28.57 33.78 0 bottom
R159  0  [0402]  38.48 42.55 0 bottom
R160  1K  [0402]  33.66 18.92 0 top
R161  49.9k  [0402]  49.66 22.48 90 top
R162  10k  [0402]  51.94 6.35 90 top
R163  10k  [0603]  69.09 17.53 0 top
R164  3.16k  [0402]  53.09 6.35 90 top
R165  86.6k  [0402]  54.36 6.35 90 top
R166  1.74k  [0402]  55.59 25.55 90 top
R167  5.62k  [0603]  66.29 15.24 270 top
R168  0  [0805]  81.03 6.48 180 top
R169  0  [0805]  72.9 30.99 270 top
R170  0  [0805]  82.04 7.49 90 top
R171  20k  [0402]  89.28 26.04 90 top
R172  0  [0805]  73.91 32 180 top
R173  21.5k  [0402]  79.76 28.57 180 top
R174  3.65k  [0402]  85.47 24.64 90 bottom
R175  8.25k  [0402]  86.11 8.89 0 top
R176  10k  [0402]  77.34 27.43 180 top
R177  4.87k  [0805]  100.84 21.21 270 top
R178  28k  [0402]  103.38 21.46 90 top
R179  4.75k  [0805]  100.84 17.65 270 top
R180  6.81k  [0805]  6.35 80.39 180 top
R181  4.02k  [0805]  2.79 80.39 180 top
R182  11.8k  [0805]  45.09 19.18 180 top
R183  4.02k  [0805]  42.29 18.29 270 top
R184  0  [0603]  27.18 144.02 270 bottom
R185  0  [0603]  28.83 144.02 90 bottom
R186  0  [0402]  16.48 103 0 top
R187  0  [0402]  16.92 100.03 90 top
R188  390  [0402]  15.11 98.55 180 bottom
R189  6.81k  [0402]  20.45 90.81 90 top
R190  47k  [0402]  5.97 116.33 90 bottom
R191  100  [0402]  28.45 37.34 270 bottom
R192  100  [0402]  30.73 37.34 270 bottom
R193  100  [0402]  37.47 41.15 0 bottom
R194  0  [0201]  117.93 86.13 0 top
R195  0  [0201]  117.93 86.89 0 top
R196  0  [0201]  117.93 83.54 180 top
R197  0  [0201]  117.93 84.3 180 top
SW1  MSP INP  [SW_THVT_SPST_PTS635SL43]  5.97 134.75 270 top
SW2  MSP RST  [SW_THVT_SPST_PTS635SL43]  5.97 122.17 270 top
SW3  PWR ON/OFF  [SW_SMVT_SPST_ES02]  9.22 24.36 90 top
T1  TC1-1-43X+  [TFMR_5_150X150_50]  62.09 86.36 315 bottom
TP1  ORN  [TP_THVT_100_RND]  83.31 129.16 0 top
TP2  ORN  [TP_THVT_100_RND]  78.87 129.16 0 top
TP3  ORN  [TP_THVT_100_RND]  69.98 129.16 180 top
TP4  ORN  [TP_THVT_100_RND]  74.42 129.16 180 top
TP5  ORN  [TP_THVT_100_RND]  36.7 136.65 0 top
TP6  ORN  [TP_THVT_100_RND]  42.04 42.8 0 top
TP7  ORN  [TP_THVT_100_RND]  42.04 38.35 0 top
TP8  ORN  [TP_THVT_100_RND]  42.04 33.91 0 top
TP9  ORN  [TP_THVT_100_RND]  30.61 112.01 0 top
TP10  RED  [TP_THVT_125_RND_063D]  25.02 3.3 0 top
TP11  BLK  [TP_THVT_125_RND_063D]  16.64 3.17 0 top
TP12  BLK  [TP_THVT_100_RND]  94.36 17.27 0 top
TP13  BLK  [TP_THVT_100_RND]  37.72 35.69 0 top
TP14  BLK  [TP_THVT_100_RND]  14.2 134.49 0 top
TP15  BLK  [TP_THVT_100_RND]  65.53 129.16 180 top
TP16  ORN  [TP_THVT_100_RND]  94.36 11.43 0 top
TP17  ORN  [TP_THVT_100_RND]  17.4 95.38 0 top
TP18  ORN  [TP_THVT_100_RND]  25.73 86.23 0 top
TP19  ORN  [TP_THVT_100_RND]  84.12 66.29 0 top
U1  LMH5401-SP  [LCCC_14_5P5X6MM_1P27]  53.97 105.4 225 top
U2  LMH5401-SP  [LCCC_14_5P5X6MM_1P27]  53.99 65.29 315 top
U3  LMC6762  [SOIC_8_197X157_50]  19.81 61.85 180 top
U4  ADC12DJ1620  [ADC12D1620QML-SP]  83.31 85.34 0 top
U5  TMP461-SP  [CFP_10_270X276_50_PWRPAD]  71.63 116.28 90 top
U6  CDCLVP111-SP  [CQFP_HFG_36_0P635MM]  97.23 114.2 0 top
U7  LMX2615-SP  [CQFP_64_429X429_0P5MM]  26.04 129.03 270 bottom
U8  24LC65  [SO_8_207X207_50]  105.11 37.57 180 bottom
U9  SN74AVC4T774  [TSSOP_16_201X177_26]  55.75 33.66 180 bottom
U10  TLV70233  [SOT_5_120X69_37]  12.95 36.96 0 bottom
U11  SN74LVC1G125DBVR  [SOT_5_120X69_57]  29.84 46.35 180 top
U12  FT4232HL  [LQFP_64_402X402_20]  28.45 45.59 0 bottom
U13  93LC46B-I  [MSOP_8_118X118_0P65MM]  25.4 33.91 270 bottom
U14  TPS2400  [DBV5]  28.19 21.34 270 bottom
U15  TPS50601A-SP  [CFP_20_300X510_50_PWRPAD]  57.53 15.88 90 top
U16  TPS7H1101A-SP  [DUAL_FLATPACK_TPS7H1101-SP]  82.28 18.25 90 top
U17  LP2953QML-SP  [CFP_NAC_16_0P5MM]  102.74 17.53 270 bottom
U18  TPS7A4501-SP  [CFP_10_270X276_50_PWRPAD]  5.33 70.23 90 top
U19  TPS7A4501-SP  [CFP_10_270X276_50_PWRPAD]  45.59 9.02 90 top
U20  MSP430FR5969-SP  [QFN_48_281X281_0P50MM_RGZ]  13.44 103.89 90 bottom
U21  LMT01  [LMT01-SP]  23.57 89.66 90 bottom
U22  LMT01  [LMT01-SP]  84.12 69.85 90 bottom
Y1  100.0000MHz  [OSC_6_SM_SIA0006B]  27.3 147.7 270 bottom
Y2  12MHz, 18pF  [XTAL_2_SM_126X197]  17.91 42.29 270 bottom
Y3  32.768KHZ  [XTAL_2_SM_MS3V-T1R_264X55]  24.89 103.68 180 bottom
Y4  4MHz  [XTAL_HC-49UX]  24.1 101.24 90 top

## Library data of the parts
C1 C2 C6 C14 C16 C17 C24 C29 C136-C138 C140 C142 C144 = CAP_0402_0.1uF_H
C3 C13 C18 C23 C197 = CAP_0201_10000pF
C4 C7 C19 C21 = CAP_0402_1pF
C5 C8 C20 C22 = CAP_0402_2.7pF
C9 C11 C25 C27 = CAP_0306_0.01uF
C10 C12 C26 C28 = CAP_0306_2200pF
C15 = CAP_0402_0.01uF
C30 C35 C156 C157 C165 C166 = CAP_0603_0.1uF
C31 C45 C163 C167 C170 C237 = CAP_0603_1uF
C32 C33 C38-C43 C128 C133 C135 C139 = CAP_0402_4700pF_H
C34 C37 = CAP_0603_100pF
C36 C77 C96 C113 C123 = CAP_TANT_B_10uF_10V: tolerance: 20%
C44 C208 C211 C219 C222 C229 = CAP0201_0: tolerance: 10%
C46-C52 C55 C56 C63-C76 C78-C95 C97-C112 C114-C122 C124-C126 C221 C223 C230 = CAP0402_0: tolerance: 10%
C53 C54 C57-C62 C181 = CAP NP_1: tolerance: 10%
C127 C150-C155 C193 C202 = CAP NP_1: tolerance: 20%
C129 C147 C148 = CAP NP_0: tolerance: 20%
C130 = CAP NP_0
C131 C132 C134 = CAP NP_0: tolerance: 10%
C141 C143 C145 C146 C149 = CAP_0402_4700pF_H: tolerance: 20%
C158 C160 C169 = CAP_0603_10uF
C159 C161 C162 C171-C173 C176-C179 C189 C233 C236 = CAP_0201_0.1uF
C164 C168 = CAP_1206_100uF_6.3V
C174 C175 C231 C232 C234 C235 = CAP_0402_18pF
C180 = CAP POL-B_0: tolerance: 10%
C182 = CAP_1206_2.2uF
C183 = CAP_0805_10uF_10V
C184 = CAP_0805_0.1uF_X7R_50V
C185 C198 = CAP_0805_.1uF_25V
C186 = CAP_1206_47uF
C187 = CAP_TANT_D_220uF_6.3V: tolerance: 10%
C188 = CAP_0805_9.0pF
C190 = CAP_0805_91pF_50V
C191 = CAP_0805_.027uF_50V
C192 C194-C196 C200 C201 C218 = CAP0201_0: tolerance: 20%
C199 = CAP_TANT_D_220uF_6.3V: tolerance: 20%
C203 C209 C212 C220 = CAP0603: tolerance: 10%
C204 = CAP_0805_1000pF_25V
C205 = CAP_0201_2200pF
C206 C213 C224 = CAP_TANT_X_15uF_50V: tolerance: 20%
C207 C214 C225 = CAP_0805_1uF_50V
C210 = CAP_1210_.1uF_50V: tolerance: 10%, 50V, X7R
C215 C226 = CAP_0805_470pF
C216 C227 = CAP_TANT_X_15uF_50V: tolerance: 10%
C217 C228 = CAP_1210_.1uF_50V
C238 = CAP_0402_0.001uF_H
D1 D3 = LED_ORANGE_0603
D2 D4 = DIODE_1N4148W
D5 = LED_RED_0
D6 D10 = LED
D7 D8 = LED_GREEN_0
D9 = DIODE_MBRB2515L
F1 = FUSE_0
FB1 FB2 = FERRITE_BEAD_0603_120_H
FB3 = FERRITE_BEAD_0603_26_H
FB4 FB5 = BEAD_NFM31P
FB6-FB10 = FERRITE_BEAD_0402_H
J1-J6 J13-J22 J26 J27 = SMA_THVT_SMA_CENTER_PIN
J7-J12 J24 J34 J35 = HEADER_1x2_0
J28 = CON_SMVT_40X10_SEAM
J29 J31 JP1 JP2 = JUMPER_1X2_100
J30 = HEADER_1x4_100
J32 = USB_MINI_AB_MNE20-5G5P10
J33 = CONN JACK PWR
J36 = HEADER_2x7_100
JP3-JP13 = JUMPER_1X3_100
L1-L8 = IND_0603_H_0
L9 L10 = IND_0402_H_0
L11 = IND_POWER_1.5uH
MT1-MT4 = MOUNTING_HOLE
PP1-PP18 = PROBE_POINT_0
Q1 = CSD18532Q5B
R1 R12 R16 R27 = Res_0201_Zero_H
R2 R11 R17 R24 = Res_0402_127
R3 R7 R18 R25 = Res_0402_22.6
R4 R9 R19 R23 = Res_0402_40.2_H
R5 R8 R20 R26 R39 R41 = Res_0603_1.3k_H
R6 R22 R122-R126 R133 R134 R136 R138 R143 R149-R151 R155 R191-R193 = Res_0603_100_H
R10 R21 R91 R96 = Res_0402_51_.5%
R13 R28 R32 R33 R38 R47 R48 R110 R111 R119 R141 R142 R145-R147 R176 = Res_0402_10k
R14 R15 = Res_0603_1k
R29 R30 R35 R40 R46 R54-R57 R102 = Res_0402_1k
R31 R36 = Res_0402_1M
R34 R37 = Res_0402_1.2k
R42 R44 = Res_0402_3.3k_.1%_H: tolerance: .1%
R43 R45 R98 R101 R103 R106 R108 R109 R116 R120 R127 R128 R130 R184 R185 = Res_0402_Zero_H
R49 = Res_0603_750_H
R51 = Res_0402_100k_H
R53 R70 R79 R93 R105 = Res_0402_100_H
R61 R62 R67 R68 R71 R72 R77 R78 = Res_0402_249
R64 R65 R73 R75 R80-R84 R89 R90 R92 R94 R186 R187 R194-R197 = Res_0603_Zero_H
R85-R88 = Res_0805_Zero_H
R95 = Res_0402_68
R97 R99 R100 R104 = Res_0402_49.9
R107 R188 = Res_0402_330
R112 R189 = Res_0402_4.99K
R113 = Res_0201_100
R114 R115 = Res_0402_Zero
R117 R121 R129 R131 R139 R144 R153 R156 R159 R168-R170 R172 = Res_0402_Zero_H_DNI
R118 = Res_0402_270
R132 = Res_0603_Zero
R135 R137 = Res_0603_10
R140 = Res_0603_12k
R148 = Res_0603_1k_H
R157 = Res_0603_2.2k
R160 = Res_0402_1k: tolerance: 1%
R161 = Res_0402_49.9k
R162 R178 = Res_0402_28k_H
R163 = Res_0402_10k_H
R164 = Res_0402_9.31k_H
R165 = Res_0402_86.6k_H
R166 = Res_0402_1.82k
R167 = Res_0805_4.87k
R171 = Res_0402_20K_H
R173 = Res_0402_21.5k
R174 = Res_0402_3.65K_H
R175 = Res_0402_8.25: tolerance: 1%
R177 R180 R182 = Res_0805_6.81k
R179 R181 R183 = Res_0805_4.02k
R190 = R_0: tolerance: 1%
SW1 SW2 = SW PUSHBUTTON
SW3 = SW KEY-SPST_1
T1 = TFMR_5_TC1-1-43X+
TP1-TP9 TP16-TP19 = TESTPOINT_ORANGE
TP10 = TESTLOOP_BLACK
TP11-TP15 = TESTPOINT_BLK
U1 U2 = LMH5401-SP
U3 = LMC6762
U4 = ADC12DJ1620-QML
U5 = TMP461_0
U6 = CDCLVP111-SP
U7 = LMX2615-SP
U8 = 24LC65
U9 = SN74AVC4T774
U10 = TLV702
U11 = SN74LVC1G125DBVR
U12 = FT4232HL
U13 = EEPROM_93LC46B
U14 = TPS2400
U15 = TPS50601A-SP_0
U16 = TPS7H1101-SP
U17 = LP2953QML-SP
U18 U19 = TPS7A4501-SP
U20 = MSP430FR5969-SP
U21 U22 = LMT01
Y1 = OSC_6_SM_VECTRON_VC-708_0
Y2 Y3 = CRYSTAL_ABM3_0
Y4 = CRYSTAL_ABM3_0: Tolerance: ***; User Part Number: ***

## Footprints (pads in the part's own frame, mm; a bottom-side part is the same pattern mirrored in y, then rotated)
0201
  rect 0.305x0.305 smd: 1(-0.305,0) 2(0.305,0)
0306
  rect 0.356x1.626 smd: 1(-0.363,0) 2(0.363,0)
0402
  rect 0.508x0.635 smd: 1(-0.508,0) 2(0.508,0)
0603
  rect 0.762x0.813 smd: 1(-0.787,0) 2(0.787,0)
0805
  rect 1.016x1.27 smd: 1(-1.016,0) 2(1.016,0)
1206
  rect 1.27x1.6 smd: 1(-1.524,0) 2(1.524,0)
1206_BEAD_NFM31P
  rect 1.016x1.575 smd: 1(-1.778,0) 3(1.778,0)
  rect 1.321x2.032 smd: 2(0,0)
1210
  rect 0.965x2.489 smd: 1(-1.372,0) 2(1.372,0)
7343
  rect 2.388x2.642 smd: 1(-3.404,0) 2(3.404,0)
ADC12D1620QML-SP
  round 0.889 smd: A1(-12.065,12.065) A2(-10.795,12.065) A3(-9.525,12.065) A4(-8.255,12.065) A5(-6.985,12.065) A6(-5.715,12.065) A7(-4.445,12.065) A8(-3.175,12.065) A9(-1.905,12.065) A10(-0.635,12.065) A11(0.635,12.065) A12(1.905,12.065) A13(3.175,12.065) A14(4.445,12.065) A15(5.715,12.065) A16(6.985,12.065) A17(8.255,12.065) A18(9.525,12.065) A19(10.795,12.065) A20(12.065,12.065) B1(-12.065,10.795) B2(-10.795,10.795) B3(-9.525,10.795) B4(-8.255,10.795) B5(-6.985,10.795) B6(-5.715,10.795) B7(-4.445,10.795) B8(-3.175,10.795) B9(-1.905,10.795) B10(-0.635,10.795) B11(0.635,10.795) B12(1.905,10.795) B13(3.175,10.795) B14(4.445,10.795) B15(5.715,10.795) B16(6.985,10.795) B17(8.255,10.795) B18(9.525,10.795) B19(10.795,10.795) B20(12.065,10.795) C1(-12.065,9.525) C2(-10.795,9.525) C3(-9.525,9.525) C4(-8.255,9.525) C5(-6.985,9.525) C6(-5.715,9.525) C7(-4.445,9.525) C8(-3.175,9.525) C9(-1.905,9.525) C10(-0.635,9.525) C11(0.635,9.525) C12(1.905,9.525) C13(3.175,9.525) C14(4.445,9.525) C15(5.715,9.525) C16(6.985,9.525) C17(8.255,9.525) C18(9.525,9.525) C19(10.795,9.525) C20(12.065,9.525) D1(-12.065,8.255) D2(-10.795,8.255) D3(-9.525,8.255) D4(-8.255,8.255) D5(-6.985,8.255) D6(-5.715,8.255) D7(-4.445,8.255) D8(-3.175,8.255) D9(-1.905,8.255) D10(-0.635,8.255) D11(0.635,8.255) D12(1.905,8.255) D13(3.175,8.255) D14(4.445,8.255) D15(5.715,8.255) D16(6.985,8.255) D17(8.255,8.255) D18(9.525,8.255) D19(10.795,8.255) D20(12.065,8.255) E1(-12.065,6.985) E2(-10.795,6.985) E3(-9.525,6.985) E4(-8.255,6.985) E17(8.255,6.985) E18(9.525,6.985) E19(10.795,6.985) E20(12.065,6.985) F1(-12.065,5.715) F2(-10.795,5.715) F3(-9.525,5.715) F4(-8.255,5.715) F17(8.255,5.715) F18(9.525,5.715) F19(10.795,5.715) F20(12.065,5.715) G1(-12.065,4.445) G2(-10.795,4.445) G3(-9.525,4.445) G4(-8.255,4.445) G17(8.255,4.445) G18(9.525,4.445) G19(10.795,4.445) G20(12.065,4.445) H1(-12.065,3.175) H2(-10.795,3.175) H3(-9.525,3.175) H4(-8.255,3.175) H17(8.255,3.175) H18(9.525,3.175) H19(10.795,3.175) H20(12.065,3.175) J1(-12.065,1.905) J2(-10.795,1.905) J3(-9.525,1.905) J4(-8.255,1.905) J17(8.255,1.905) J18(9.525,1.905) J19(10.795,1.905) J20(12.065,1.905) K1(-12.065,0.635) K2(-10.795,0.635) K3(-9.525,0.635) K4(-8.255,0.635) K17(8.255,0.635) K18(9.525,0.635) K19(10.795,0.635) K20(12.065,0.635) L1(-12.065,-0.635) L2(-10.795,-0.635) L3(-9.525,-0.635) L4(-8.255,-0.635) L17(8.255,-0.635) L18(9.525,-0.635) L19(10.795,-0.635) L20(12.065,-0.635) M1(-12.065,-1.905) M2(-10.795,-1.905) M3(-9.525,-1.905) M4(-8.255,-1.905) M17(8.255,-1.905) M18(9.525,-1.905) M19(10.795,-1.905) M20(12.065,-1.905) N1(-12.065,-3.175) N2(-10.795,-3.175) N3(-9.525,-3.175) N4(-8.255,-3.175) N17(8.255,-3.175) N18(9.525,-3.175) N19(10.795,-3.175) N20(12.065,-3.175) P1(-12.065,-4.445) P2(-10.795,-4.445) P3(-9.525,-4.445) P4(-8.255,-4.445) P17(8.255,-4.445) P18(9.525,-4.445) P19(10.795,-4.445) P20(12.065,-4.445) R1(-12.065,-5.715) R2(-10.795,-5.715) R3(-9.525,-5.715) R4(-8.255,-5.715) R17(8.255,-5.715) R18(9.525,-5.715) R19(10.795,-5.715) R20(12.065,-5.715) T1(-12.065,-6.985) T2(-10.795,-6.985) T3(-9.525,-6.985) T4(-8.255,-6.985) T17(8.255,-6.985) T18(9.525,-6.985) T19(10.795,-6.985) T20(12.065,-6.985) U1(-12.065,-8.255) U2(-10.795,-8.255) U3(-9.525,-8.255) U4(-8.255,-8.255) U5(-6.985,-8.255) U6(-5.715,-8.255) U7(-4.445,-8.255) U8(-3.175,-8.255) U9(-1.905,-8.255) U10(-0.635,-8.255) U11(0.635,-8.255) U12(1.905,-8.255) U13(3.175,-8.255) U14(4.445,-8.255) U15(5.715,-8.255) U16(6.985,-8.255) U17(8.255,-8.255) U18(9.525,-8.255) U19(10.795,-8.255) U20(12.065,-8.255) V1(-12.065,-9.525) V2(-10.795,-9.525) V3(-9.525,-9.525) V4(-8.255,-9.525) V5(-6.985,-9.525) V6(-5.715,-9.525) V7(-4.445,-9.525) V8(-3.175,-9.525) V9(-1.905,-9.525) V10(-0.635,-9.525) V11(0.635,-9.525) V12(1.905,-9.525) V13(3.175,-9.525) V14(4.445,-9.525) V15(5.715,-9.525) V16(6.985,-9.525) V17(8.255,-9.525) V18(9.525,-9.525) V19(10.795,-9.525) V20(12.065,-9.525) W1(-12.065,-10.795) W2(-10.795,-10.795) W3(-9.525,-10.795) W4(-8.255,-10.795) W5(-6.985,-10.795) W6(-5.715,-10.795) W7(-4.445,-10.795) W8(-3.175,-10.795) W9(-1.905,-10.795) W10(-0.635,-10.795) W11(0.635,-10.795) W12(1.905,-10.795) W13(3.175,-10.795) W14(4.445,-10.795) W15(5.715,-10.795) W16(6.985,-10.795) W17(8.255,-10.795) W18(9.525,-10.795) W19(10.795,-10.795) W20(12.065,-10.795) Y1(-12.065,-12.065) Y2(-10.795,-12.065) Y3(-9.525,-12.065) Y4(-8.255,-12.065) Y5(-6.985,-12.065) Y6(-5.715,-12.065) Y7(-4.445,-12.065) Y8(-3.175,-12.065) Y9(-1.905,-12.065) Y10(-0.635,-12.065) Y11(0.635,-12.065) Y12(1.905,-12.065) Y13(3.175,-12.065) Y14(4.445,-12.065) Y15(5.715,-12.065) Y16(6.985,-12.065) Y17(8.255,-12.065) Y18(9.525,-12.065) Y19(10.795,-12.065) Y20(12.065,-12.065)
  round 0.81 smd: AA2(-4,5) AA3(-3,5) AA4(-2,5) AA5(-1,5) AA6(0,5) AA7(1,5) AA8(2,5) AA9(3,5) AA10(4,5) AA11(5,5) AB1(-5,4) AB2(-4,4) AB3(-3,4) AB4(-2,4) AB5(-1,4) AB6(0,4) AB7(1,4) AB8(2,4) AB9(3,4) AB10(4,4) AB11(5,4) AC1(-5,3) AC2(-4,3) AC3(-3,3) AC4(-2,3) AC5(-1,3) AC6(0,3) AC7(1,3) AC8(2,3) AC9(3,3) AC10(4,3) AC11(5,3) AD1(-5,2) AD2(-4,2) AD3(-3,2) AD4(-2,2) AD5(-1,2) AD6(0,2) AD7(1,2) AD8(2,2) AD9(3,2) AD10(4,2) AD11(5,2) AE1(-5,1) AE2(-4,1) AE3(-3,1) AE4(-2,1) AE5(-1,1) AE6(0,1) AE7(1,1) AE8(2,1) AE9(3,1) AE10(4,1) AE11(5,1) AF1(-5,0) AF2(-4,0) AF3(-3,0) AF4(-2,0) AF5(-1,0) AF6(0,0) AF7(1,0) AF8(2,0) AF9(3,0) AF10(4,0) AF11(5,0) AG1(-5,-1) AG2(-4,-1) AG3(-3,-1) AG4(-2,-1) AG5(-1,-1) AG6(0,-1) AG7(1,-1) AG8(2,-1) AG9(3,-1) AG10(4,-1) AG11(5,-1) AH1(-5,-2) AH2(-4,-2) AH3(-3,-2) AH4(-2,-2) AH5(-1,-2) AH6(0,-2) AH7(1,-2) AH8(2,-2) AH9(3,-2) AH10(4,-2) AH11(5,-2) AJ1(-5,-3) AJ2(-4,-3) AJ3(-3,-3) AJ4(-2,-3) AJ5(-1,-3) AJ6(0,-3) AJ7(1,-3) AJ8(2,-3) AJ9(3,-3) AJ10(4,-3) AJ11(5,-3) AK1(-5,-4) AK2(-4,-4) AK3(-3,-4) AK4(-2,-4) AK5(-1,-4) AK6(0,-4) AK7(1,-4) AK8(2,-4) AK9(3,-4) AK10(4,-4) AK11(5,-4) AL1(-5,-5) AL2(-4,-5) AL3(-3,-5) AL4(-2,-5) AL5(-1,-5) AL6(0,-5) AL7(1,-5) AL8(2,-5) AL9(3,-5) AL10(4,-5) AL11(5,-5)
CFP_10_270X276_50_PWRPAD
  rect 1.422x0.551 smd: 1(-5.893,2.54) 2(-5.893,1.27) 3(-5.893,0) 4(-5.893,-1.27) 5(-5.893,-2.54) 6(5.893,-2.54) 7(5.893,-1.27) 8(5.893,0) 9(5.893,1.27) 10(5.893,2.54)
  rect 4.318x6.604 smd: 11(0,0)
CFP_20_300X510_50_PWRPAD
  rect 1.422x0.551 smd: 1(-7.061,5.715) 2(-7.061,4.445) 3(-7.061,3.175) 4(-7.061,1.905) 5(-7.061,0.635) 6(-7.061,-0.635) 7(-7.074,-1.905) 8(-7.074,-3.175) 9(-7.074,-4.445) 10(-7.074,-5.715) 11(7.061,-5.715) 12(7.061,-4.445) 13(7.061,-3.175) 14(7.061,-1.905) 15(7.061,-0.635) 16(7.061,0.635) 17(7.061,1.905) 18(7.061,3.175) 19(7.061,4.445) 20(7.061,5.715)
  rect 4.318x8.89 smd: 21(0,0)
CFP_NAC_16_0P5MM
  rect 2.286x0.483 smd: 1(-5.334,4.445) 2(-5.334,3.175) 3(-5.334,1.905) 4(-5.334,0.635) 5(-5.334,-0.635) 6(-5.334,-1.905) 7(-5.334,-3.175) 8(-5.334,-4.445) 9(5.334,-4.445) 10(5.334,-3.175) 11(5.334,-1.905) 12(5.334,-0.635) 13(5.334,0.635) 14(5.334,1.905) 15(5.334,3.175) 16(5.334,4.445)
CON_RAPC722_JACK_THVT_3
  round 4.318 hole 3.556: 1(0,3.124)
  round 3.81 hole 3.048: 2(0,-3.124) 3(4.801,0.127)
CON_SMRT_USBMNE20_F
  round 1.27 hole 0.889 unplated: (0.65,-2.2) (0.65,2.2)
  rect 2.311x0.508 smd: 1(3.45,1.6) 2(3.45,0.8) 3(3.45,0) 4(3.45,-0.8) 5(3.45,-1.6)
  rect 2.489x2.007 smd: 6(-2.15,-4.45) 7(3.35,-4.45) 8(3.35,4.45) 9(-2.15,4.45)
CON_SMVT_40X10_SEAM_MTG
  round 3.81 hole 2.692: (-31.496,-2.007) (31.496,-2.007)
  round 1.27 hole 1.27 unplated: (-27.191,-3.048) (27.191,0)
  round 0.635 smd: A1(24.765,5.715) A2(23.495,5.715) A3(22.225,5.715) A4(20.955,5.715) A5(19.685,5.715) A6(18.415,5.715) A7(17.145,5.715) A8(15.875,5.715) A9(14.605,5.715) A10(13.335,5.715) A11(12.065,5.715) A12(10.795,5.715) A13(9.525,5.715) A14(8.255,5.715) A15(6.985,5.715) A16(5.715,5.715) A17(4.445,5.715) A18(3.175,5.715) A19(1.905,5.715) A20(0.635,5.715) A21(-0.635,5.715) A22(-1.905,5.715) A23(-3.175,5.715) A24(-4.445,5.715) A25(-5.715,5.715) A26(-6.985,5.715) A27(-8.255,5.715) A28(-9.525,5.715) A29(-10.795,5.715) A30(-12.065,5.715) A31(-13.335,5.715) A32(-14.605,5.715) A33(-15.875,5.715) A34(-17.145,5.715) A35(-18.415,5.715) A36(-19.685,5.715) A37(-20.955,5.715) A38(-22.225,5.715) A39(-23.495,5.715) A40(-24.765,5.715) B1(24.765,4.445) B2(23.495,4.445) B3(22.225,4.445) B4(20.955,4.445) B5(19.685,4.445) B6(18.415,4.445) B7(17.145,4.445) B8(15.875,4.445) B9(14.605,4.445) B10(13.335,4.445) B11(12.065,4.445) B12(10.795,4.445) B13(9.525,4.445) B14(8.255,4.445) B15(6.985,4.445) B16(5.715,4.445) B17(4.445,4.445) B18(3.175,4.445) B19(1.905,4.445) B20(0.635,4.445) B21(-0.635,4.445) B22(-1.905,4.445) B23(-3.175,4.445) B24(-4.445,4.445) B25(-5.715,4.445) B26(-6.985,4.445) B27(-8.255,4.445) B28(-9.525,4.445) B29(-10.795,4.445) B30(-12.065,4.445) B31(-13.335,4.445) B32(-14.605,4.445) B33(-15.875,4.445) B34(-17.145,4.445) B35(-18.415,4.445) B36(-19.685,4.445) B37(-20.955,4.445) B38(-22.225,4.445) B39(-23.495,4.445) B40(-24.765,4.445) C1(24.765,3.175) C2(23.495,3.175) C3(22.225,3.175) C4(20.955,3.175) C5(19.685,3.175) C6(18.415,3.175) C7(17.145,3.175) C8(15.875,3.175) C9(14.605,3.175) C10(13.335,3.175) C11(12.065,3.175) C12(10.795,3.175) C13(9.525,3.175) C14(8.255,3.175) C15(6.985,3.175) C16(5.715,3.175) C17(4.445,3.175) C18(3.175,3.175) C19(1.905,3.175) C20(0.635,3.175) C21(-0.635,3.175) C22(-1.905,3.175) C23(-3.175,3.175) C24(-4.445,3.175) C25(-5.715,3.175) C26(-6.985,3.175) C27(-8.255,3.175) C28(-9.525,3.175) C29(-10.795,3.175) C30(-12.065,3.175) C31(-13.335,3.175) C32(-14.605,3.175) C33(-15.875,3.175) C34(-17.145,3.175) C35(-18.415,3.175) C36(-19.685,3.175) C37(-20.955,3.175) C38(-22.225,3.175) C39(-23.495,3.175) C40(-24.765,3.175) D1(24.765,1.905) D2(23.495,1.905) D3(22.225,1.905) D4(20.955,1.905) D5(19.685,1.905) D6(18.415,1.905) D7(17.145,1.905) D8(15.875,1.905) D9(14.605,1.905) D10(13.335,1.905) D11(12.065,1.905) D12(10.795,1.905) D13(9.525,1.905) D14(8.255,1.905) D15(6.985,1.905) D16(5.715,1.905) D17(4.445,1.905) D18(3.175,1.905) D19(1.905,1.905) D20(0.635,1.905) D21(-0.635,1.905) D22(-1.905,1.905) D23(-3.175,1.905) D24(-4.445,1.905) D25(-5.715,1.905) D26(-6.985,1.905) D27(-8.255,1.905) D28(-9.525,1.905) D29(-10.795,1.905) D30(-12.065,1.905) D31(-13.335,1.905) D32(-14.605,1.905) D33(-15.875,1.905) D34(-17.145,1.905) D35(-18.415,1.905) D36(-19.685,1.905) D37(-20.955,1.905) D38(-22.225,1.905) D39(-23.495,1.905) D40(-24.765,1.905) E1(24.765,0.635) E2(23.495,0.635) E3(22.225,0.635) E4(20.955,0.635) E5(19.685,0.635) E6(18.415,0.635) E7(17.145,0.635) E8(15.875,0.635) E9(14.605,0.635) E10(13.335,0.635) E11(12.065,0.635) E12(10.795,0.635) E13(9.525,0.635) E14(8.255,0.635) E15(6.985,0.635) E16(5.715,0.635) E17(4.445,0.635) E18(3.175,0.635) E19(1.905,0.635) E20(0.635,0.635) E21(-0.635,0.635) E22(-1.905,0.635) E23(-3.175,0.635) E24(-4.445,0.635) E25(-5.715,0.635) E26(-6.985,0.635) E27(-8.255,0.635) E28(-9.525,0.635) E29(-10.795,0.635) E30(-12.065,0.635) E31(-13.335,0.635) E32(-14.605,0.635) E33(-15.875,0.635) E34(-17.145,0.635) E35(-18.415,0.635) E36(-19.685,0.635) E37(-20.955,0.635) E38(-22.225,0.635) E39(-23.495,0.635) E40(-24.765,0.635) F1(24.765,-0.635) F2(23.495,-0.635) F3(22.225,-0.635) F4(20.955,-0.635) F5(19.685,-0.635) F6(18.415,-0.635) F7(17.145,-0.635) F8(15.875,-0.635) F9(14.605,-0.635) F10(13.335,-0.635) F11(12.065,-0.635) F12(10.795,-0.635) F13(9.525,-0.635) F14(8.255,-0.635) F15(6.985,-0.635) F16(5.715,-0.635) F17(4.445,-0.635) F18(3.175,-0.635) F19(1.905,-0.635) F20(0.635,-0.635) F21(-0.635,-0.635) F22(-1.905,-0.635) F23(-3.175,-0.635) F24(-4.445,-0.635) F25(-5.715,-0.635) F26(-6.985,-0.635) F27(-8.255,-0.635) F28(-9.525,-0.635) F29(-10.795,-0.635) F30(-12.065,-0.635) F31(-13.335,-0.635) F32(-14.605,-0.635) F33(-15.875,-0.635) F34(-17.145,-0.635) F35(-18.415,-0.635) F36(-19.685,-0.635) F37(-20.955,-0.635) F38(-22.225,-0.635) F39(-23.495,-0.635) F40(-24.765,-0.635) G1(24.765,-1.905) G2(23.495,-1.905) G3(22.225,-1.905) G4(20.955,-1.905) G5(19.685,-1.905) G6(18.415,-1.905) G7(17.145,-1.905) G8(15.875,-1.905) G9(14.605,-1.905) G10(13.335,-1.905) G11(12.065,-1.905) G12(10.795,-1.905) G13(9.525,-1.905) G14(8.255,-1.905) G15(6.985,-1.905) G16(5.715,-1.905) G17(4.445,-1.905) G18(3.175,-1.905) G19(1.905,-1.905) G20(0.635,-1.905) G21(-0.635,-1.905) G22(-1.905,-1.905) G23(-3.175,-1.905) G24(-4.445,-1.905) G25(-5.715,-1.905) G26(-6.985,-1.905) G27(-8.255,-1.905) G28(-9.525,-1.905) G29(-10.795,-1.905) G30(-12.065,-1.905) G31(-13.335,-1.905) G32(-14.605,-1.905) G33(-15.875,-1.905) G34(-17.145,-1.905) G35(-18.415,-1.905) G36(-19.685,-1.905) G37(-20.955,-1.905) G38(-22.225,-1.905) G39(-23.495,-1.905) G40(-24.765,-1.905) H1(24.765,-3.175) H2(23.495,-3.175) H3(22.225,-3.175) H4(20.955,-3.175) H5(19.685,-3.175) H6(18.415,-3.175) H7(17.145,-3.175) H8(15.875,-3.175) H9(14.605,-3.175) H10(13.335,-3.175) H11(12.065,-3.175) H12(10.795,-3.175) H13(9.525,-3.175) H14(8.255,-3.175) H15(6.985,-3.175) H16(5.715,-3.175) H17(4.445,-3.175) H18(3.175,-3.175) H19(1.905,-3.175) H20(0.635,-3.175) H21(-0.635,-3.175) H22(-1.905,-3.175) H23(-3.175,-3.175) H24(-4.445,-3.175) H25(-5.715,-3.175) H26(-6.985,-3.175) H27(-8.255,-3.175) H28(-9.525,-3.175) H29(-10.795,-3.175) H30(-12.065,-3.175) H31(-13.335,-3.175) H32(-14.605,-3.175) H33(-15.875,-3.175) H34(-17.145,-3.175) H35(-18.415,-3.175) H36(-19.685,-3.175) H37(-20.955,-3.175) H38(-22.225,-3.175) H39(-23.495,-3.175) H40(-24.765,-3.175) J1(24.765,-4.445) J2(23.495,-4.445) J3(22.225,-4.445) J4(20.955,-4.445) J5(19.685,-4.445) J6(18.415,-4.445) J7(17.145,-4.445) J8(15.875,-4.445) J9(14.605,-4.445) J10(13.335,-4.445) J11(12.065,-4.445) J12(10.795,-4.445) J13(9.525,-4.445) J14(8.255,-4.445) J15(6.985,-4.445) J16(5.715,-4.445) J17(4.445,-4.445) J18(3.175,-4.445) J19(1.905,-4.445) J20(0.635,-4.445) J21(-0.635,-4.445) J22(-1.905,-4.445) J23(-3.175,-4.445) J24(-4.445,-4.445) J25(-5.715,-4.445) J26(-6.985,-4.445) J27(-8.255,-4.445) J28(-9.525,-4.445) J29(-10.795,-4.445) J30(-12.065,-4.445) J31(-13.335,-4.445) J32(-14.605,-4.445) J33(-15.875,-4.445) J34(-17.145,-4.445) J35(-18.415,-4.445) J36(-19.685,-4.445) J37(-20.955,-4.445) J38(-22.225,-4.445) J39(-23.495,-4.445) J40(-24.765,-4.445) K1(24.765,-5.715) K2(23.495,-5.715) K3(22.225,-5.715) K4(20.955,-5.715) K5(19.685,-5.715) K6(18.415,-5.715) K7(17.145,-5.715) K8(15.875,-5.715) K9(14.605,-5.715) K10(13.335,-5.715) K11(12.065,-5.715) K12(10.795,-5.715) K13(9.525,-5.715) K14(8.255,-5.715) K15(6.985,-5.715) K16(5.715,-5.715) K17(4.445,-5.715) K18(3.175,-5.715) K19(1.905,-5.715) K20(0.635,-5.715) K21(-0.635,-5.715) K22(-1.905,-5.715) K23(-3.175,-5.715) K24(-4.445,-5.715) K25(-5.715,-5.715) K26(-6.985,-5.715) K27(-8.255,-5.715) K28(-9.525,-5.715) K29(-10.795,-5.715) K30(-12.065,-5.715) K31(-13.335,-5.715) K32(-14.605,-5.715) K33(-15.875,-5.715) K34(-17.145,-5.715) K35(-18.415,-5.715) K36(-19.685,-5.715) K37(-20.955,-5.715) K38(-22.225,-5.715) K39(-23.495,-5.715) K40(-24.765,-5.715)
CON_THVT_2X7_100_M_SHROUDED_KEY
  rect 1.676x1.676 hole 0.914: 1(0,2.54)
  round 1.676 hole 0.914: 2(2.54,2.54) 3(0,0) 4(2.54,0) 5(0,-2.54) 6(2.54,-2.54) 7(0,-5.08) 8(2.54,-5.08) 9(0,-7.62) 10(2.54,-7.62) 11(0,-10.16) 12(2.54,-10.16) 13(0,-12.7) 14(2.54,-12.7)
CQFP_64_429X429_0P5MM
  rect 2.15x0.3 smd: 1(-7.15,3.753) 2(-7.15,3.252) 3(-7.15,2.752) 4(-7.15,2.252) 5(-7.15,1.751) 6(-7.15,1.251) 7(-7.15,0.751) 8(-7.15,0.25) 9(-7.15,-0.25) 10(-7.15,-0.751) 11(-7.15,-1.251) 12(-7.15,-1.751) 13(-7.15,-2.252) 14(-7.15,-2.752) 15(-7.15,-3.252) 16(-7.15,-3.753) 33(7.15,-3.753) 34(7.15,-3.252) 35(7.15,-2.752) 36(7.15,-2.252) 37(7.15,-1.751) 38(7.15,-1.251) 39(7.15,-0.751) 40(7.15,-0.25) 41(7.15,0.25) 42(7.15,0.751) 43(7.15,1.251) 44(7.15,1.751) 45(7.15,2.252) 46(7.15,2.752) 47(7.15,3.252) 48(7.15,3.753)
  rect 0.3x2.15 smd: 17(-3.753,-7.15) 18(-3.252,-7.15) 19(-2.752,-7.15) 20(-2.252,-7.15) 21(-1.751,-7.15) 22(-1.251,-7.15) 23(-0.751,-7.15) 24(-0.25,-7.15) 25(0.25,-7.15) 26(0.751,-7.15) 27(1.251,-7.15) 28(1.751,-7.15) 29(2.252,-7.15) 30(2.752,-7.15) 31(3.252,-7.15) 32(3.753,-7.15) 49(3.753,7.15) 50(3.252,7.15) 51(2.752,7.15) 52(2.252,7.15) 53(1.751,7.15) 54(1.251,7.15) 55(0.751,7.15) 56(0.25,7.15) 57(-0.25,7.15) 58(-0.751,7.15) 59(-1.251,7.15) 60(-1.751,7.15) 61(-2.252,7.15) 62(-2.752,7.15) 63(-3.252,7.15) 64(-3.753,7.15)
  rect 8x8 smd: 65(0,0)
